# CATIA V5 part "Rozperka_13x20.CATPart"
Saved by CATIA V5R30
Part number: Rozperka_13x20
Definition: ISO 13337-13x20_3
Nomenclature: ISO 13337-13x20_3
Source: Unknown
Description: PART--DESC
Bounding box of the stored display mesh (mm): x -136 to -123.025, y -24.994 to -12.006, z 29.7 to 49.7
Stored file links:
  E:\Bakalarka\Model\Forma_v7\Rozperka_13x20.CATPart
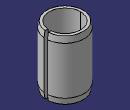
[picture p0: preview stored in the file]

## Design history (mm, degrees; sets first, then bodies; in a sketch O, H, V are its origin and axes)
Body1 "MANIFOLD_SOLID_BREP #3674" (main body)
  Solid1: solid without history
